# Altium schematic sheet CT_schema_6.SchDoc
size 282 x 245 mm
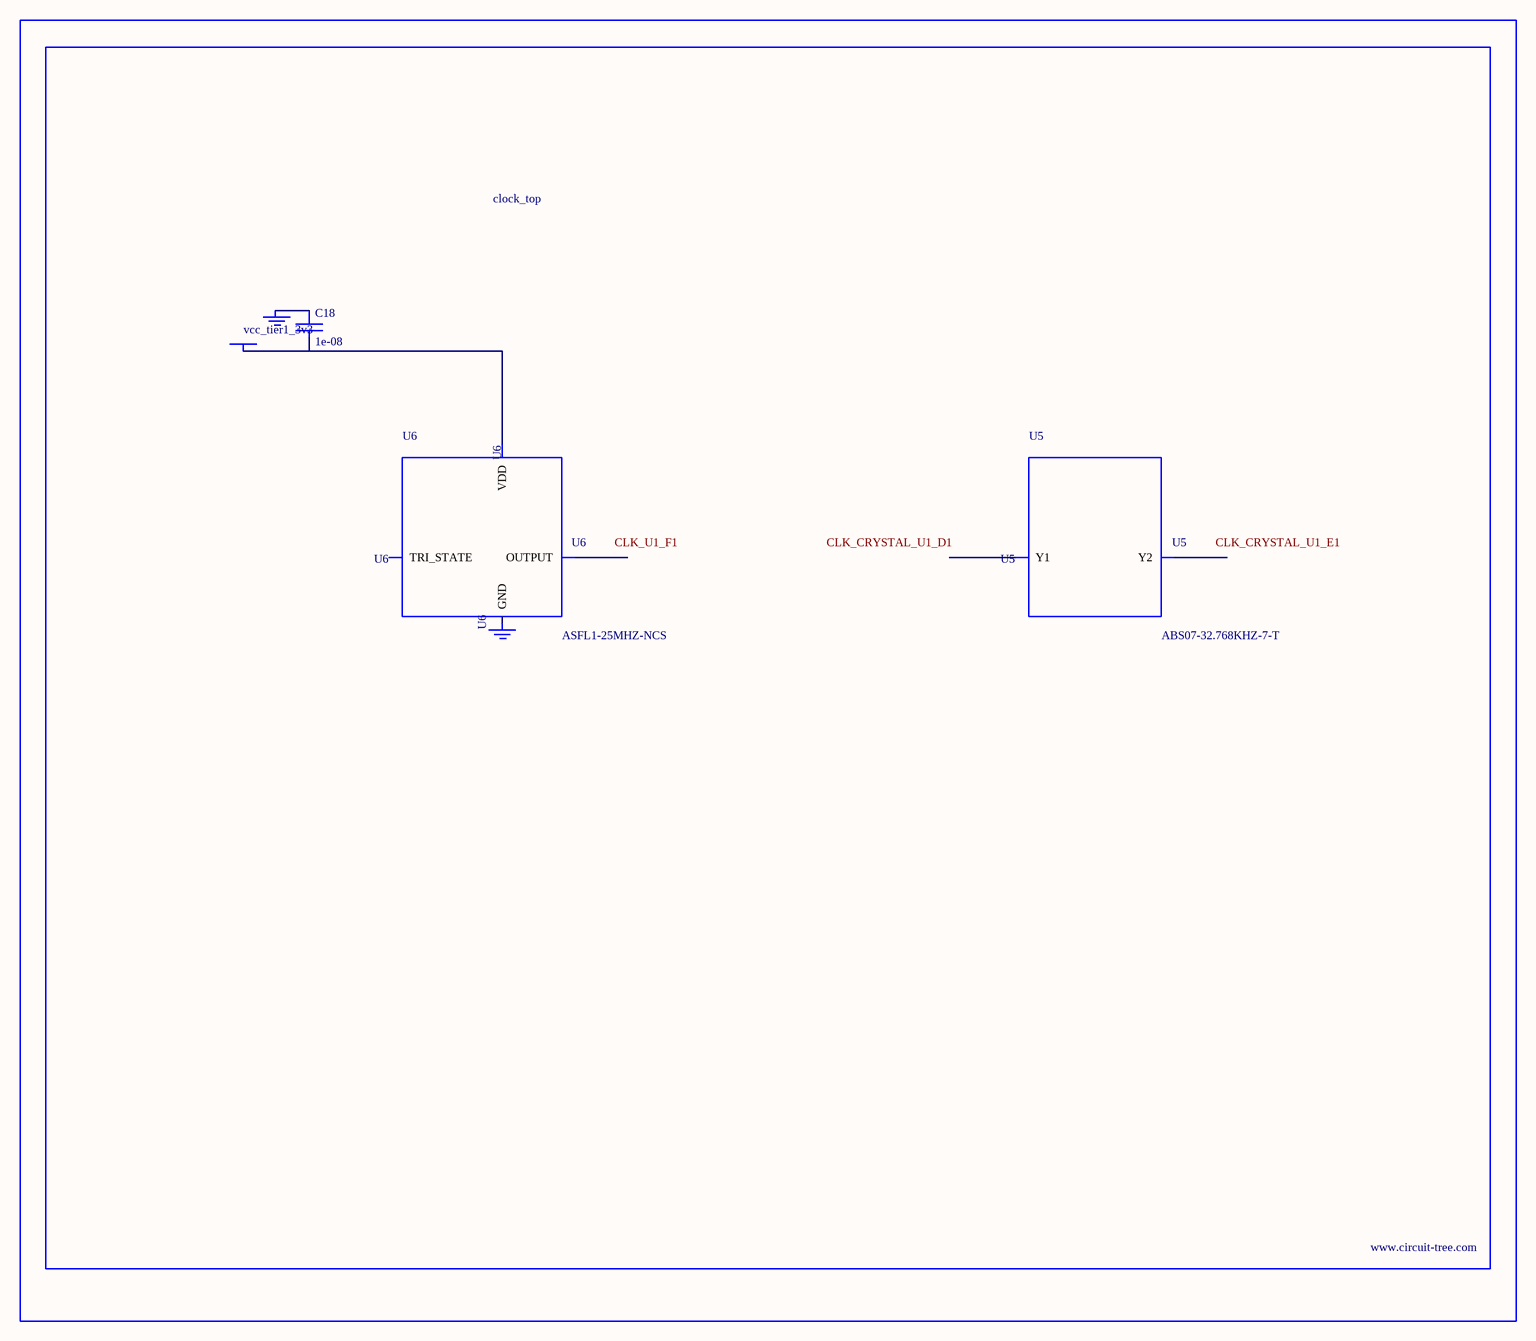
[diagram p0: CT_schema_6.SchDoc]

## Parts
BORDER5  (no value)
C18  1e-08  [C0402]
GND_INSTANCE_5_0  (no value)
GND_INSTANCE_5_1  (no value)
POWER_INSTANCE_5_0  vcc_tier1_3v3
U5  ABS07-32.768KHZ-7-T  [ABS07-32.768KHZ-7-T]
U6  ASFL1-25MHZ-NCS  [ASFL1]

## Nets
NetC18_1: C18.1 GND_INSTANCE_5_0.0(GND)
NetC18_2: C18.2 POWER_INSTANCE_5_0.0(PWR) U6.4(VDD)

Not connected (* = marked no-connect by the designer): GND_INSTANCE_5_1 0(GND); U5 1(Y1) 2(Y2); U6 1(TRI_STATE) 2(GND) 3(OUTPUT)

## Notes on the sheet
- Labels drawn without touching a wire or pin: CLK_CRYSTAL_U1_D1, CLK_CRYSTAL_U1_E1, CLK_U1_F1

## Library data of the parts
BORDER5 = BORDER_PAGE5
C18 = C0402C103K3RAC
GND_INSTANCE_5_0 GND_INSTANCE_5_1 = GND
POWER_INSTANCE_5_0 = PWR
